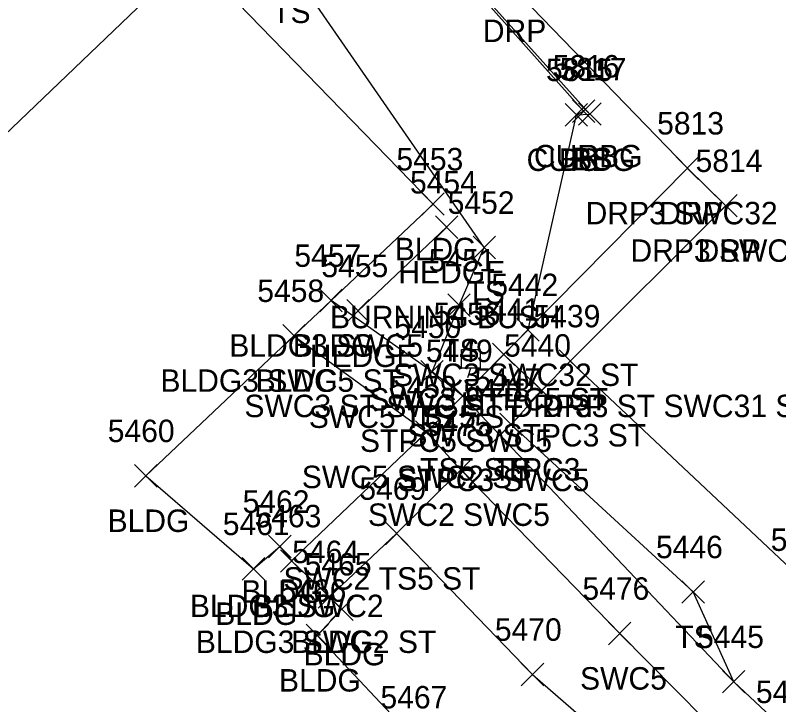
# Model space of a CAD drawing. Extents: x 1618146 to 1620418, y 640749 to 641927.
# Drawn here: x 1620177.9 to 1620245.8, y 641199.7 to 641261.1 of the extents above; entities that cross this region are included whole.
import ezdxf

# ---------------------------------------------------------------- set-up
doc = ezdxf.new("R2010")
doc.units = 0
for name, color, linetype in [('L_A', 7, 'Continuous'), ('L_C', 7, 'Continuous'), ('L_I', 7, 'Continuous'), ('L_TIC', 7, 'Continuous'), ('LAHR', 7, 'Continuous'), ('LBC', 7, 'Continuous'), ('LBF', 7, 'Continuous'), ('LELB', 7, 'Continuous'), ('P_I', 7, 'Continuous'), ('R_A', 7, 'Continuous'), ('R_I', 7, 'Continuous'), ('R_TIC', 7, 'Continuous'), ('RC', 7, 'Continuous'), ('RDP', 7, 'Continuous'), ('RSW', 7, 'Continuous'), ('U_A', 7, 'Continuous'), ('U_I', 7, 'Continuous'), ('ULP', 7, 'Continuous')]:
    doc.layers.add(name, color=color, linetype=linetype)

msp = doc.modelspace()

# ---------------------------------------------------------------- linework, layer by layer
at = {"layer": 'L_TIC'}
for points in [[(1620226.8, 641251.254), (1620228.8, 641253.254)], [(1620228.8, 641251.254), (1620226.8, 641253.254)], [(1620228.009, 641251.317), (1620230.009, 641253.317)], [(1620230.009, 641251.317), (1620228.009, 641253.317)], [(1620214.058, 641243.302), (1620216.058, 641245.302)], [(1620216.058, 641243.302), (1620214.058, 641245.302)], [(1620214.058, 641243.302), (1620216.058, 641245.302)], [(1620216.058, 641243.302), (1620214.058, 641245.302)], [(1620215.265, 641241.246), (1620217.265, 641243.246)], [(1620217.265, 641241.246), (1620215.265, 641243.246)], [(1620218.618, 641239.432), (1620220.618, 641241.432)], [(1620220.618, 641239.432), (1620218.618, 641241.432)], [(1620204.976, 641234.712), (1620206.976, 641236.712)], [(1620206.976, 641234.712), (1620204.976, 641236.712)], [(1620216.367, 641234.303), (1620218.367, 641236.303)], [(1620218.367, 641234.303), (1620216.367, 641236.303)], [(1620207.379, 641233.793), (1620209.379, 641235.793)], [(1620209.379, 641233.793), (1620207.379, 641235.793)], [(1620201.677, 641231.585), (1620203.677, 641233.585)], [(1620203.677, 641231.585), (1620201.677, 641233.585)], [(1620220.343, 641229.922), (1620222.343, 641231.922)], [(1620222.343, 641229.922), (1620220.343, 641231.922)], [(1620213.968, 641228.37), (1620215.968, 641230.37)], [(1620215.968, 641228.37), (1620213.968, 641230.37)], [(1620223.726, 641226.716), (1620225.726, 641228.716)], [(1620225.726, 641226.716), (1620223.726, 641228.716)], [(1620216.686, 641226.233), (1620218.686, 641228.233)], [(1620218.686, 641226.233), (1620216.686, 641228.233)], [(1620220.999, 641223.681), (1620222.999, 641225.681)], [(1620222.999, 641223.681), (1620220.999, 641225.681)], [(1620220.999, 641223.681), (1620222.999, 641225.681)], [(1620222.999, 641223.681), (1620220.999, 641225.681)], [(1620220.011, 641222.739), (1620222.011, 641224.739)], [(1620222.011, 641222.739), (1620220.011, 641224.739)], [(1620188.499, 641219.107), (1620190.499, 641221.107)], [(1620190.499, 641219.107), (1620188.499, 641221.107)], [(1620210.815, 641213.968), (1620212.815, 641215.968)], [(1620212.815, 641213.968), (1620210.815, 641215.968)], [(1620200.415, 641212.808), (1620202.415, 641214.808)], [(1620202.415, 641212.808), (1620200.415, 641214.808)], [(1620201.472, 641211.521), (1620203.472, 641213.521)], [(1620203.472, 641211.521), (1620201.472, 641213.521)], [(1620198.083, 641210.828), (1620200.083, 641212.828)], [(1620200.083, 641210.828), (1620198.083, 641212.828)], [(1620237.212, 641208.768), (1620239.212, 641210.768)], [(1620239.212, 641208.768), (1620237.212, 641210.768)], [(1620204.827, 641208.331), (1620206.827, 641210.331)], [(1620206.827, 641208.331), (1620204.827, 641210.331)], [(1620205.941, 641207.229), (1620207.941, 641209.229)], [(1620207.941, 641207.229), (1620205.941, 641209.229)], [(1620203.756, 641204.896), (1620205.756, 641206.896)], [(1620205.756, 641204.896), (1620203.756, 641206.896)], [(1620222.903, 641201.414), (1620224.903, 641203.414)], [(1620224.903, 641201.414), (1620222.903, 641203.414)], [(1620240.813, 641200.772), (1620242.813, 641202.772)], [(1620242.813, 641200.772), (1620240.813, 641202.772)]]:
    msp.add_lwpolyline(points, dxfattribs=at)
at = {"layer": 'LAHR'}
msp.add_lwpolyline([(1620216.265, 641242.246), (1620208.379, 641234.793)], dxfattribs=at)
at = {"layer": 'LBC'}
for points in [[(1620215.058, 641244.302), (1620205.976, 641235.712), (1620202.677, 641232.585), (1620189.499, 641220.107), (1620199.083, 641211.828), (1620201.415, 641213.808), (1620202.472, 641212.521), (1620205.827, 641209.331), (1620206.941, 641208.229), (1620204.756, 641205.896), (1620213.685, 641196.392), (1620197.139, 641180.509), (1620189.981, 641173.967), (1620166.556, 641198.685), (1620162.715, 641202.828), (1620152.839, 641213.225), (1620141.669, 641224.901), (1620165.022, 641247.378), (1620169.209, 641243.063), (1620193.587, 641266.433)], [(1620215.058, 641244.302), (1620193.587, 641266.433)]]:
    msp.add_lwpolyline(points, dxfattribs=at)
at = {"layer": 'LBF'}
for points in [[(1620221.343, 641230.922), (1620217.686, 641227.233)], [(1620224.726, 641227.716), (1620221.999, 641224.681), (1620221.011, 641223.739)]]:
    msp.add_lwpolyline(points, dxfattribs=at)
at = {"layer": 'LELB'}
for points in [[(1620227.8, 641252.254), (1620229.009, 641252.317), (1620204.576, 641279.582), (1620191.508, 641276.753), (1620183.248, 641283.239)], [(1620214.968, 641229.37), (1620217.367, 641235.303), (1620219.618, 641240.432), (1620202.327, 641265.422), (1620193.89, 641269.411), (1620188.385, 641269.337), (1620170.25, 641260.802), (1620152.961, 641252.207)], [(1620227.8, 641252.254), (1620223.503, 641233.105)], [(1620241.813, 641201.772), (1620238.212, 641209.768), (1620221.999, 641224.681)], [(1620211.815, 641214.968), (1620223.903, 641202.414), (1620233.244, 641194.294), (1620232.558, 641185.185), (1620222.564, 641171.861), (1620213.458, 641164.948), (1620208.609, 641168.764), (1620197.139, 641180.509)]]:
    msp.add_lwpolyline(points, dxfattribs=at)
at = {"layer": 'R_TIC'}
for points in [[(1620227.453, 641251.572), (1620229.453, 641253.572)], [(1620229.453, 641251.572), (1620227.453, 641253.572)], [(1620226.8, 641251.254), (1620228.8, 641253.254)], [(1620228.8, 641251.254), (1620226.8, 641253.254)], [(1620236.691, 641246.498), (1620238.691, 641248.498)], [(1620238.691, 641246.498), (1620236.691, 641248.498)], [(1620236.691, 641246.498), (1620238.691, 641248.498)], [(1620238.691, 641246.498), (1620236.691, 641248.498)], [(1620240.112, 641243.16), (1620242.112, 641245.16)], [(1620242.112, 641243.16), (1620240.112, 641245.16)], [(1620240.112, 641243.16), (1620242.112, 641245.16)], [(1620242.112, 641243.16), (1620240.112, 641245.16)], [(1620204.976, 641234.712), (1620206.976, 641236.712)], [(1620206.976, 641234.712), (1620204.976, 641236.712)], [(1620222.503, 641232.105), (1620224.503, 641234.105)], [(1620224.503, 641232.105), (1620222.503, 641234.105)], [(1620222.503, 641232.105), (1620224.503, 641234.105)], [(1620224.503, 641232.105), (1620222.503, 641234.105)], [(1620201.677, 641231.585), (1620203.677, 641233.585)], [(1620203.677, 641231.585), (1620201.677, 641233.585)], [(1620220.343, 641229.922), (1620222.343, 641231.922)], [(1620222.343, 641229.922), (1620220.343, 641231.922)], [(1620226.266, 641229.328), (1620228.266, 641231.328)], [(1620228.266, 641229.328), (1620226.266, 641231.328)], [(1620226.266, 641229.328), (1620228.266, 641231.328)], [(1620228.266, 641229.328), (1620226.266, 641231.328)], [(1620226.266, 641229.328), (1620228.266, 641231.328)], [(1620228.266, 641229.328), (1620226.266, 641231.328)], [(1620226.266, 641229.328), (1620228.266, 641231.328)], [(1620228.266, 641229.328), (1620226.266, 641231.328)], [(1620213.968, 641228.37), (1620215.968, 641230.37)], [(1620215.968, 641228.37), (1620213.968, 641230.37)], [(1620223.726, 641226.716), (1620225.726, 641228.716)], [(1620225.726, 641226.716), (1620223.726, 641228.716)], [(1620216.686, 641226.233), (1620218.686, 641228.233)], [(1620218.686, 641226.233), (1620216.686, 641228.233)], [(1620213.484, 641223.007), (1620215.484, 641225.007)], [(1620215.484, 641223.007), (1620213.484, 641225.007)], [(1620213.484, 641223.007), (1620215.484, 641225.007)], [(1620215.484, 641223.007), (1620213.484, 641225.007)], [(1620220.011, 641222.739), (1620222.011, 641224.739)], [(1620222.011, 641222.739), (1620220.011, 641224.739)], [(1620216.542, 641219.644), (1620218.542, 641221.644)], [(1620218.542, 641219.644), (1620216.542, 641221.644)], [(1620216.542, 641219.644), (1620218.542, 641221.644)], [(1620218.542, 641219.644), (1620216.542, 641221.644)], [(1620210.815, 641213.968), (1620212.815, 641215.968)], [(1620212.815, 641213.968), (1620210.815, 641215.968)], [(1620201.472, 641211.521), (1620203.472, 641213.521)], [(1620203.472, 641211.521), (1620201.472, 641213.521)], [(1620204.827, 641208.331), (1620206.827, 641210.331)], [(1620206.827, 641208.331), (1620204.827, 641210.331)], [(1620230.667, 641205.068), (1620232.667, 641207.068)], [(1620232.667, 641205.068), (1620230.667, 641207.068)], [(1620240.813, 641200.772), (1620242.813, 641202.772)], [(1620242.813, 641200.772), (1620240.813, 641202.772)]]:
    msp.add_lwpolyline(points, dxfattribs=at)
at = {"layer": 'RC'}
msp.add_lwpolyline([(1620227.8, 641252.254), (1620228.453, 641252.572), (1620204.65, 641279.32), (1620204.098, 641278.428)], dxfattribs=at)
at = {"layer": 'RDP'}
for points in [[(1620223.069, 641293.279), (1620210.287, 641279.18), (1620221.999, 641263.73), (1620237.691, 641247.498), (1620241.112, 641244.16)], [(1620227.266, 641230.328), (1620248.37, 641210.419)]]:
    msp.add_lwpolyline(points, dxfattribs=at)
at = {"layer": 'RSW'}
for points in [[(1620223.503, 641233.105), (1620237.691, 641247.498)], [(1620227.266, 641230.328), (1620241.112, 641244.16)], [(1620247.05, 641196.867), (1620241.813, 641201.772), (1620221.011, 641223.739), (1620217.686, 641227.233), (1620214.968, 641229.37), (1620205.976, 641235.712)], [(1620202.677, 641232.585), (1620214.484, 641224.007), (1620217.542, 641220.644), (1620231.667, 641206.068), (1620244.221, 641193.357)], [(1620227.266, 641230.328), (1620224.726, 641227.716), (1620221.343, 641230.922), (1620223.503, 641233.105)], [(1620214.484, 641224.007), (1620202.472, 641212.521)], [(1620205.827, 641209.331), (1620211.815, 641214.968), (1620217.542, 641220.644)]]:
    msp.add_lwpolyline(points, dxfattribs=at)
at = {"layer": 'ULP'}
for p, q in [((1620218.583, 641232.199), (1620218.417, 641231.365)), ((1620217.583, 641229.699), (1620217.583, 641231.365)), ((1620217.583, 641231.365), (1620219.25, 641231.365)), ((1620219.25, 641231.365), (1620219.25, 641229.699)), ((1620218.417, 641230.532), (1620218.417, 641230.532)), ((1620219.25, 641229.699), (1620217.583, 641229.699)), ((1620218.167, 641228.865), (1620218.417, 641229.699))]:
    msp.add_line(p, q, dxfattribs=at)

# ---------------------------------------------------------------- texts
at = {"layer": 'L_A'}
for s, p in [('TS', (1620200.737, 641260.422)), ('BS', (1620226.241, 641247.254)), ('BS', (1620227.45, 641247.317)), ('BLDG', (1620211.648, 641239.302)), ('BLDG', (1620211.648, 641239.302)), ('HEDGE', (1620211.966, 641237.246)), ('TS', (1620218.028, 641235.432)), ('BLDG', (1620202.567, 641230.712)), ('HEDGE', (1620204.08, 641229.793)), ('TS', (1620215.777, 641230.303)), ('BLDG', (1620199.267, 641227.585)), ('SWC3 STPC5 ST', (1620209.383, 641225.922)), ('TS', (1620213.378, 641224.37)), ('SWC3 STPC3 ST', (1620212.766, 641222.716)), ('STPC5 SWC5', (1620208.553, 641222.233)), ('TS5 STPC3', (1620213.904, 641219.681)), ('TS', (1620220.408, 641219.681)), ('STPC3 SWC5', (1620211.878, 641218.739)), ('BLDG', (1620186.09, 641215.107)), ('TS', (1620210.225, 641209.968)), ('BLDG', (1620198.006, 641208.808)), ('BLDG', (1620199.062, 641207.521)), ('BLDG', (1620195.673, 641206.828)), ('TS', (1620236.621, 641204.768)), ('BLDG', (1620202.418, 641204.331)), ('BLDG', (1620203.532, 641203.229)), ('BLDG', (1620201.346, 641200.896))]:
    msp.add_text(s, height=2, dxfattribs=at).set_placement(p)
at = {"layer": 'L_C'}
msp.add_text('BURNING BUSH', height=2, dxfattribs=at).set_placement((1620205.888, 641233.246))
at = {"layer": 'L_I'}
for s, p in [('5815', (1620225.107, 641255.254)), ('5817', (1620226.316, 641255.317)), ('5453', (1620211.798, 641247.302)), ('5453', (1620211.798, 641247.302)), ('5454', (1620213.006, 641245.246)), ('5452', (1620216.359, 641243.432)), ('5457', (1620202.717, 641238.712)), ('5451', (1620214.674, 641238.303)), ('5455', (1620205.12, 641237.793)), ('5458', (1620199.417, 641235.585)), ('5441', (1620218.651, 641233.922)), ('5450', (1620211.622, 641232.37)), ('5440', (1620221.38, 641230.716)), ('5449', (1620214.419, 641230.233)), ('5447', (1620218.739, 641227.681)), ('5447', (1620218.739, 641227.681)), ('5448', (1620217.752, 641226.739)), ('5460', (1620186.106, 641223.107)), ('5469', (1620208.5, 641217.968)), ('5462', (1620198.108, 641216.808)), ('5463', (1620199.165, 641215.521)), ('5461', (1620196.343, 641214.828)), ('5464', (1620202.52, 641212.331)), ('5446', (1620234.897, 641212.768)), ('5465', (1620203.634, 641211.229)), ('5466', (1620201.394, 641208.896)), ('5470', (1620220.557, 641205.414)), ('5445', (1620238.553, 641204.772)), ('5467', (1620210.378, 641199.392))]:
    msp.add_text(s, height=2, dxfattribs=at).set_placement(p)
at = {"layer": 'P_I'}
for s, p in [('5443', (1620245.111, 641213.419)), ('5444', (1620243.79, 641199.867))]:
    msp.add_text(s, height=2, dxfattribs=at).set_placement(p)
at = {"layer": 'R_A'}
for s, p in [('DRP', (1620219.487, 641258.73)), ('CURBG', (1620224.036, 641247.572)), ('CURBG', (1620223.382, 641247.254)), ('DRP3 SWC32', (1620228.636, 641242.498)), ('DRP', (1620235.18, 641242.498)), ('DRP3 SWC31', (1620232.624, 641239.16)), ('DRP', (1620238.601, 641239.16)), ('BLDG3 SWC5', (1620196.921, 641230.712)), ('SWC3 SWC32 ST', (1620211.496, 641228.105)), ('SWC3 SWC32 ST', (1620211.496, 641228.105)), ('BLDG3 SWC5 ST', (1620190.795, 641227.585)), ('SWC3 STPC5 ST', (1620209.383, 641225.922)), ('SWC3 ST SWC ST DRP33 ST SWC31 ST', (1620198.266, 641225.328)), ('SWC3 ST SWC ST DRP33 ST SWC31 ST', (1620198.266, 641225.328)), ('SWC3 ST SWC ST DRP33 ST SWC31 ST', (1620198.266, 641225.328)), ('DRP', (1620224.754, 641225.328)), ('SWC5 TS25 ST', (1620204, 641224.37)), ('SWC3 STPC3 ST', (1620212.766, 641222.716)), ('STPC5 SWC5', (1620208.553, 641222.233)), ('SWC5 SWC2 ST', (1620203.374, 641219.007)), ('SWC5 SWC2 ST', (1620203.374, 641219.007)), ('STPC3 SWC5', (1620211.878, 641218.739)), ('SWC2 SWC5', (1620209.259, 641215.644)), ('SWC2 SWC5', (1620209.259, 641215.644)), ('SWC2 TS5 ST', (1620201.744, 641209.968)), ('BLDG3 SWC2', (1620193.417, 641207.521)), ('BLDG3 SWC2 ST', (1620193.946, 641204.331)), ('SWC5', (1620228.14, 641201.068))]:
    msp.add_text(s, height=2, dxfattribs=at).set_placement(p)
at = {"layer": 'R_I'}
for s, p in [('5815', (1620225.107, 641255.254)), ('5816', (1620225.705, 641255.572)), ('5813', (1620234.999, 641250.498)), ('5813', (1620234.999, 641250.498)), ('5814', (1620238.42, 641247.16)), ('5814', (1620238.42, 641247.16)), ('5457', (1620202.717, 641238.712)), ('5442', (1620220.244, 641236.105)), ('5442', (1620220.244, 641236.105)), ('5458', (1620199.417, 641235.585)), ('5441', (1620218.651, 641233.922)), ('5439', (1620223.998, 641233.328)), ('5439', (1620223.998, 641233.328)), ('5439', (1620223.998, 641233.328)), ('5439', (1620223.998, 641233.328)), ('5450', (1620211.622, 641232.37)), ('5440', (1620221.38, 641230.716)), ('5449', (1620214.419, 641230.233)), ('5459', (1620211.216, 641227.007)), ('5459', (1620211.216, 641227.007)), ('5448', (1620217.752, 641226.739)), ('5475', (1620214.282, 641223.644)), ('5475', (1620214.282, 641223.644)), ('5469', (1620208.5, 641217.968)), ('5463', (1620199.165, 641215.521)), ('5443', (1620245.111, 641213.419)), ('5464', (1620202.52, 641212.331)), ('5476', (1620228.352, 641209.068)), ('5445', (1620238.553, 641204.772)), ('5444', (1620243.79, 641199.867))]:
    msp.add_text(s, height=2, dxfattribs=at).set_placement(p)
at = {"layer": 'U_A'}
msp.add_text('LI', height=2, dxfattribs=at).set_placement((1620217.519, 641225.532))
at = {"layer": 'U_I'}
msp.add_text('5456', height=2, dxfattribs=at).set_placement((1620215.102, 641233.532))

doc.saveas('drawing.dxf')
